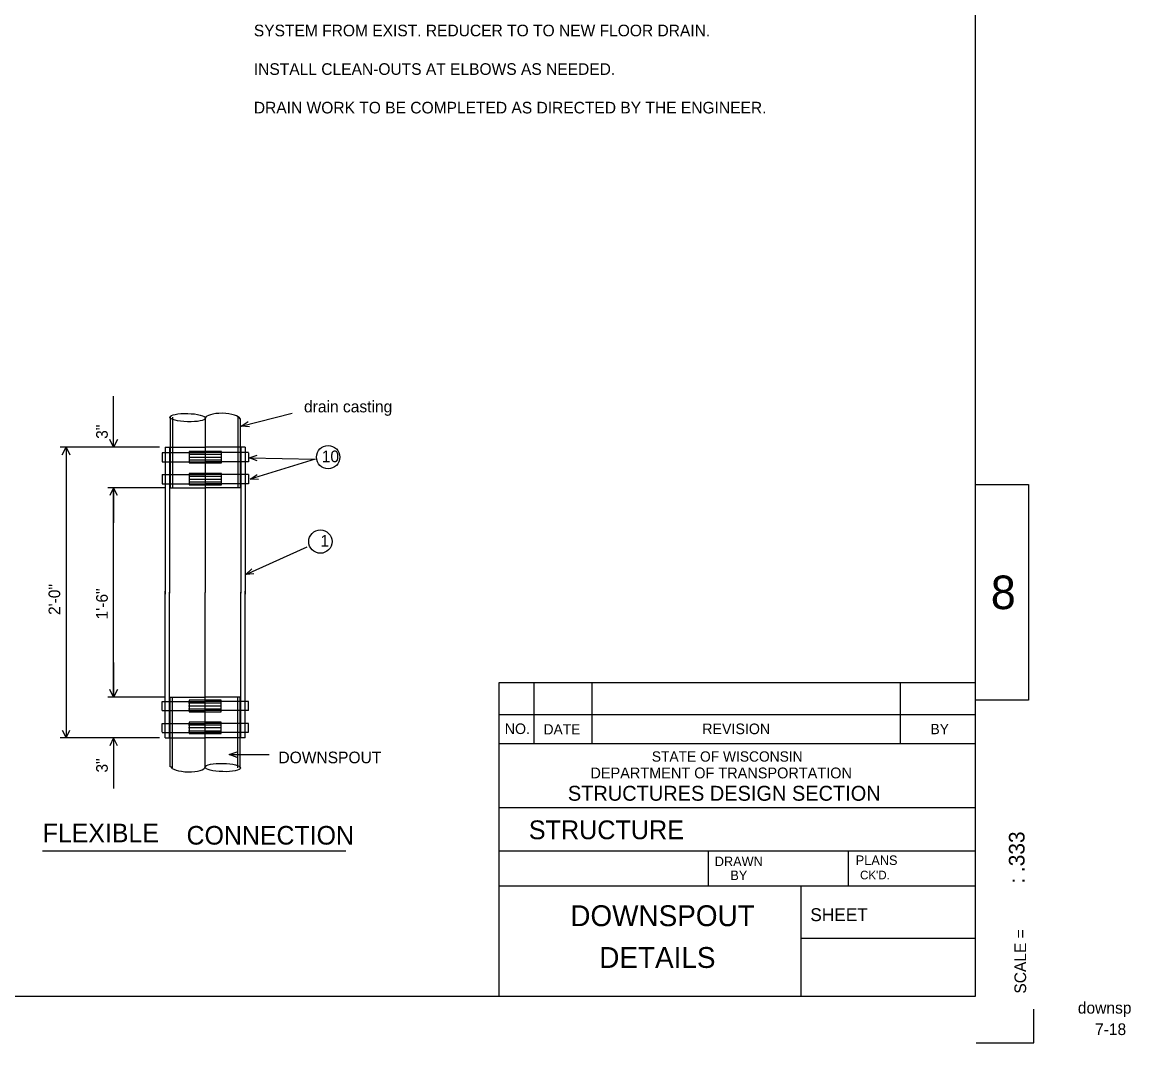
# Model space of a CAD drawing. Extents: x 15000 to 15012.1, y 999.8 to 1007.9.
# Drawn here: x 15008.092 to 15012.061, y 1000.122 to 1003.777 of the extents above; entities that cross this region are included whole.
import ezdxf

# ---------------------------------------------------------------- set-up
doc = ezdxf.new("R2010")
doc.units = 0
doc.layers.add('Level 1', color=7, linetype='Continuous')
doc.layers.add('Level 2', color=7, linetype='Continuous')

msp = doc.modelspace()

# ---------------------------------------------------------------- linework, layer by layer
at = {"layer": 'Level 1'}
for p, q in [((15011.5058, 1000.2885), (15011.5058, 1007.2814)), ((15009.7995, 1001.4123), (15011.507, 1001.4123)), ((15009.7995, 1001.1938), (15009.7995, 1001.4123)), ((15009.9255, 1001.1938), (15009.9255, 1001.4123)), ((15010.1336, 1001.1938), (15010.1336, 1001.4123)), ((15011.2365, 1001.1938), (15011.2365, 1001.4123)), ((15009.7995, 1001.2978), (15011.507, 1001.2978)), ((15009.7995, 1000.2885), (15009.7995, 1001.1938)), ((15009.7995, 1001.1938), (15011.507, 1001.1938)), ((15009.7995, 1000.965), (15011.507, 1000.965)), ((15009.7995, 1000.8089), (15011.507, 1000.8089)), ((15010.5489, 1000.684), (15010.5489, 1000.8089)), ((15011.0506, 1000.684), (15011.0506, 1000.8089)), ((15009.7995, 1000.684), (15011.507, 1000.684)), ((15010.8816, 1000.2885), (15010.8816, 1000.6839)), ((15010.8818, 1000.4966), (15011.5058, 1000.4966)), ((15001.0578, 1000.2885), (15011.5058, 1000.2885)), ((15011.714, 1000.122), (15011.714, 1000.2428)), ((15011.5083, 1000.122), (15011.714, 1000.122))]:
    msp.add_line(p, q, dxfattribs=at)
msp.add_lwpolyline([(15011.5059, 1002.1216), (15011.6948, 1002.1216), (15011.6948, 1001.3486), (15011.5059, 1001.3486)], close=True, dxfattribs=at)
at = {"layer": 'Level 2'}
for p, q in [((15008.4198, 1002.2546), (15008.4198, 1002.4371)), ((15008.6228, 1002.3621), (15008.6228, 1002.2546)), ((15008.6309, 1002.3617), (15008.6309, 1002.1096)), ((15008.7478, 1002.3643), (15008.7478, 1001.7342)), ((15008.8648, 1002.3617), (15008.8648, 1002.1096)), ((15008.8728, 1002.3576), (15008.8728, 1002.2546)), ((15008.8761, 1002.3304), (15009.0593, 1002.3762)), ((15008.8761, 1002.3304), (15008.9011, 1002.3467)), ((15008.9058, 1002.3278), (15008.8761, 1002.3304)), ((15008.5841, 1002.2546), (15008.2285, 1002.2546)), ((15008.2493, 1002.2546), (15008.2493, 1001.2137)), ((15008.5841, 1002.2546), (15008.3989, 1002.2546)), ((15008.5934, 1002.2353), (15008.6921, 1002.2353)), ((15008.5934, 1002.2342), (15008.5934, 1002.2025)), ((15008.6049, 1002.2546), (15008.748, 1002.2546)), ((15008.6049, 1002.2546), (15008.6049, 1002.2342)), ((15008.6049, 1002.2339), (15008.6049, 1002.2037)), ((15008.6049, 1002.2331), (15008.6049, 1002.2038)), ((15008.6204, 1002.2546), (15008.6204, 1001.7326)), ((15008.6228, 1002.2546), (15008.6228, 1002.1092)), ((15008.8072, 1002.2288), (15008.6912, 1002.2288)), ((15008.6921, 1002.2353), (15008.7473, 1002.2353)), ((15008.8908, 1002.2546), (15008.7477, 1002.2546)), ((15008.8058, 1002.2353), (15008.7483, 1002.2353)), ((15008.9023, 1002.2353), (15008.8058, 1002.2353)), ((15008.8728, 1002.2546), (15008.8728, 1002.1092)), ((15008.8752, 1002.2546), (15008.8752, 1001.7326)), ((15008.8908, 1002.2546), (15008.8908, 1002.2342)), ((15008.8908, 1002.2339), (15008.8908, 1002.2037)), ((15008.8908, 1002.2331), (15008.8908, 1002.2038)), ((15008.9023, 1002.2342), (15008.9023, 1002.2025)), ((15008.5934, 1002.2025), (15008.6921, 1002.2025)), ((15008.6049, 1002.2021), (15008.6049, 1002.1568)), ((15008.8072, 1002.2178), (15008.6912, 1002.2178)), ((15008.8072, 1002.2078), (15008.6912, 1002.2078)), ((15008.6921, 1002.2025), (15008.7475, 1002.2025)), ((15008.8058, 1002.2025), (15008.7481, 1002.2025)), ((15008.9023, 1002.2025), (15008.8058, 1002.2025)), ((15008.8908, 1002.2021), (15008.8908, 1002.1568)), ((15008.9054, 1002.2168), (15008.9338, 1002.2258)), ((15008.9054, 1002.2168), (15009.1418, 1002.2113)), ((15008.9333, 1002.2063), (15008.9054, 1002.2168)), ((15009.1418, 1002.2113), (15008.9091, 1002.1398)), ((15008.5934, 1002.1568), (15008.5934, 1002.124)), ((15008.5934, 1002.1568), (15008.6921, 1002.1568)), ((15008.6049, 1002.1554), (15008.6049, 1002.1251)), ((15008.8072, 1002.1502), (15008.6912, 1002.1502)), ((15008.6921, 1002.1568), (15008.7473, 1002.1568)), ((15008.8058, 1002.1568), (15008.7483, 1002.1568)), ((15008.9023, 1002.1568), (15008.8058, 1002.1568)), ((15008.8908, 1002.1554), (15008.8908, 1002.1251)), ((15008.9023, 1002.1568), (15008.9023, 1002.124)), ((15008.9091, 1002.1398), (15008.9332, 1002.1573)), ((15008.602, 1002.1092), (15008.3989, 1002.1092)), ((15008.4198, 1001.3592), (15008.4198, 1002.1092)), ((15008.4198, 1002.1092), (15008.4198, 1001.9842)), ((15008.5934, 1002.124), (15008.6921, 1002.124)), ((15008.6049, 1002.1243), (15008.6049, 1001.7288)), ((15008.6228, 1002.1092), (15008.7462, 1002.1092)), ((15008.8072, 1002.1393), (15008.6912, 1002.1393)), ((15008.8072, 1002.1293), (15008.6912, 1002.1293)), ((15008.6921, 1002.124), (15008.7475, 1002.124)), ((15008.8058, 1002.124), (15008.7481, 1002.124)), ((15008.8728, 1002.1092), (15008.7495, 1002.1092)), ((15008.9023, 1002.124), (15008.8058, 1002.124)), ((15008.8908, 1002.1243), (15008.8908, 1001.7288)), ((15008.9389, 1002.1388), (15008.9091, 1002.1398)), ((15008.8926, 1001.7989), (15009.1125, 1001.8978)), ((15008.8926, 1001.7989), (15008.9143, 1001.8193)), ((15008.9223, 1001.8016), (15008.8926, 1001.7989)), ((15008.6049, 1001.344), (15008.6049, 1001.7395)), ((15008.6204, 1001.2137), (15008.6204, 1001.7357)), ((15008.7478, 1001.104), (15008.7478, 1001.7342)), ((15008.8752, 1001.2137), (15008.8752, 1001.7357)), ((15008.8908, 1001.344), (15008.8908, 1001.7395)), ((15008.4198, 1001.4842), (15008.4198, 1001.3592)), ((15008.602, 1001.3592), (15008.3989, 1001.3592)), ((15008.6228, 1001.3592), (15008.7462, 1001.3592)), ((15008.6228, 1001.2137), (15008.6228, 1001.3592)), ((15008.6309, 1001.1066), (15008.6309, 1001.3587)), ((15008.8728, 1001.3592), (15008.7495, 1001.3592)), ((15008.8648, 1001.1066), (15008.8648, 1001.3587)), ((15008.8728, 1001.2137), (15008.8728, 1001.3592)), ((15008.5934, 1001.3116), (15008.5934, 1001.3443)), ((15008.5934, 1001.3443), (15008.6898, 1001.3443)), ((15008.6049, 1001.3129), (15008.6049, 1001.3432)), ((15008.6884, 1001.3391), (15008.8044, 1001.3391)), ((15008.6884, 1001.329), (15008.8044, 1001.329)), ((15008.6884, 1001.3181), (15008.8044, 1001.3181)), ((15008.6898, 1001.3443), (15008.7475, 1001.3443)), ((15008.8036, 1001.3443), (15008.7481, 1001.3443)), ((15008.9023, 1001.3443), (15008.8036, 1001.3443)), ((15008.8908, 1001.3129), (15008.8908, 1001.3432)), ((15008.9023, 1001.3116), (15008.9023, 1001.3443)), ((15008.5934, 1001.3116), (15008.6898, 1001.3116)), ((15008.6049, 1001.2663), (15008.6049, 1001.3116)), ((15008.6898, 1001.3116), (15008.7473, 1001.3116)), ((15008.8036, 1001.3116), (15008.7483, 1001.3116)), ((15008.9023, 1001.3116), (15008.8036, 1001.3116)), ((15008.8908, 1001.2663), (15008.8908, 1001.3116)), ((15008.5934, 1001.2342), (15008.5934, 1001.2658)), ((15008.5934, 1001.2658), (15008.6898, 1001.2658)), ((15008.6049, 1001.2343), (15008.6049, 1001.2647)), ((15008.6049, 1001.2352), (15008.6049, 1001.2645)), ((15008.6884, 1001.2605), (15008.8044, 1001.2605)), ((15008.6884, 1001.2505), (15008.8044, 1001.2505)), ((15008.6884, 1001.2396), (15008.8044, 1001.2396)), ((15008.6898, 1001.2658), (15008.7475, 1001.2658)), ((15008.8036, 1001.2658), (15008.7481, 1001.2658)), ((15008.9023, 1001.2658), (15008.8036, 1001.2658)), ((15008.8908, 1001.2343), (15008.8908, 1001.2647)), ((15008.8908, 1001.2352), (15008.8908, 1001.2645)), ((15008.9023, 1001.2342), (15008.9023, 1001.2658)), ((15008.3989, 1001.2137), (15008.2285, 1001.2137)), ((15008.5841, 1001.2137), (15008.3989, 1001.2137)), ((15008.4198, 1001.2137), (15008.4198, 1001.0325)), ((15008.5934, 1001.233), (15008.6898, 1001.233)), ((15008.6049, 1001.2137), (15008.6049, 1001.2341)), ((15008.6049, 1001.2137), (15008.748, 1001.2137)), ((15008.6228, 1001.1108), (15008.6228, 1001.2137)), ((15008.6898, 1001.233), (15008.7473, 1001.233)), ((15008.8908, 1001.2137), (15008.7477, 1001.2137)), ((15008.8036, 1001.233), (15008.7483, 1001.233)), ((15008.9023, 1001.233), (15008.8036, 1001.233)), ((15008.8728, 1001.1063), (15008.8728, 1001.2137)), ((15008.8908, 1001.2137), (15008.8908, 1001.2341)), ((15008.8339, 1001.1538), (15008.8621, 1001.1636)), ((15008.8339, 1001.1538), (15008.9769, 1001.1538)), ((15008.8621, 1001.1441), (15008.8339, 1001.1538)), ((15008.1657, 1000.8092), (15009.2514, 1000.8092))]:
    msp.add_line(p, q, dxfattribs=at)
for points in [[(15008.4337, 1002.2823), (15008.4198, 1002.2546), (15008.4058, 1002.2823)], [(15008.2354, 1002.2268), (15008.2493, 1002.2546), (15008.2633, 1002.2268)], [(15008.4337, 1002.0814), (15008.4198, 1002.1092), (15008.4058, 1002.0814)], [(15008.4337, 1002.0814), (15008.4198, 1002.1092), (15008.4058, 1002.0814)], [(15008.4337, 1001.3869), (15008.4198, 1001.3592), (15008.4058, 1001.3869)], [(15008.4337, 1001.3869), (15008.4198, 1001.3592), (15008.4058, 1001.3869)], [(15008.2354, 1001.2414), (15008.2493, 1001.2137), (15008.2633, 1001.2414)], [(15008.4337, 1001.1859), (15008.4198, 1001.2137), (15008.4058, 1001.1859)]]:
    msp.add_lwpolyline(points, dxfattribs=at)
for points in [[(15008.8058, 1002.1982), (15008.8058, 1002.1999), (15008.8058, 1002.2366), (15008.8058, 1002.2392), (15008.6908, 1002.2392), (15008.6908, 1002.1982)], [(15008.8058, 1002.1197), (15008.8058, 1002.1214), (15008.8058, 1002.158), (15008.8058, 1002.1607), (15008.6908, 1002.1607), (15008.6908, 1002.1197)], [(15008.6898, 1001.3487), (15008.6898, 1001.3469), (15008.6898, 1001.3103), (15008.6898, 1001.3077), (15008.8049, 1001.3077), (15008.8049, 1001.3487)], [(15008.6898, 1001.2701), (15008.6898, 1001.2683), (15008.6898, 1001.2318), (15008.6898, 1001.2291), (15008.8049, 1001.2291), (15008.8049, 1001.2701)]]:
    msp.add_lwpolyline(points, close=True, dxfattribs=at)
for centre in [(15009.1877, 1002.219), (15009.1599, 1001.9167)]:
    msp.add_circle(centre, 0.0417, dxfattribs=at)
for centre, major_axis in [((15008.6848, 1002.3605), (0.0634, -0.0016)), ((15008.8108, 1001.1078), (-0.0634, 0.0016))]:
    msp.add_ellipse(centre, major_axis=major_axis, ratio=0.234609, dxfattribs=at)
for centre, major_axis in [((15008.8104, 1002.3564), (0.062, -0.0016)), ((15008.6852, 1001.1119), (-0.062, 0.0016))]:
    msp.add_ellipse(centre, major_axis=major_axis, ratio=0.314672, start_param=0.070448, end_param=3.13618, dxfattribs=at)

# ---------------------------------------------------------------- texts
at = {"layer": 'Level 1'}
for s, height, p in [('8', 0.1202, (15011.5601, 1001.6749)), ('NO.', 0.03794, (15009.8201, 1001.2276)), ('DATE', 0.03691, (15009.9591, 1001.226)), ('REVISION', 0.03802, (15010.5273, 1001.2272)), ('BY', 0.03691, (15011.3443, 1001.2271)), ('STATE OF WISCONSIN', 0.036882, (15010.3466, 1001.1288)), ('DEPARTMENT OF TRANSPORTATION', 0.03877, (15010.1268, 1001.0689)), ('STRUCTURES DESIGN SECTION', 0.053447, (15010.0461, 1000.9888)), ('STRUCTURE', 0.06735, (15009.9062, 1000.851)), ('DRAWN', 0.03405, (15010.572, 1000.7546)), ('PLANS', 0.03408, (15011.0766, 1000.7588)), ('BY', 0.03397, (15010.6278, 1000.7048)), ("CK'D.", 0.03086, (15011.0921, 1000.7073)), ('DOWNSPOUT', 0.07467, (15010.0548, 1000.5398)), ('SHEET', 0.04618, (15010.9139, 1000.5577)), ('DETAILS', 0.07467, (15010.1584, 1000.3902))]:
    msp.add_text(s, height=height, dxfattribs=at).set_placement(p)
for s, height, p in [(': .333', 0.05592, (15011.6809, 1000.6918)), ('SCALE =          ', 0.041625, (15011.6866, 1000.2982))]:
    msp.add_text(s, height=height, rotation=90, dxfattribs=at).set_placement(p)
at = {"layer": 'Level 2'}
for s, height, p in [('SYSTEM FROM EXIST. REDUCER TO TO NEW FLOOR DRAIN.', 0.041651, (15008.9218, 1003.7259)), ('INSTALL CLEAN-OUTS AT ELBOWS AS NEEDED.', 0.041651, (15008.9218, 1003.5878)), ('DRAIN WORK TO BE COMPLETED AS DIRECTED BY THE ENGINEER.', 0.041651, (15008.9218, 1003.4497)), ('drain casting', 0.041667, (15009.1014, 1002.3794)), ('10', 0.04167, (15009.1649, 1002.2009)), ('1', 0.0417, (15009.1601, 1001.8986)), ('DOWNSPOUT', 0.04167, (15009.0098, 1001.123)), ('FLEXIBLE', 0.06667, (15008.1657, 1000.84)), ('CONNECTION', 0.06667, (15008.6809, 1000.8318)), ('downsp', 0.04167, (15011.8717, 1000.2266)), ('7-18', 0.04167, (15011.9333, 1000.1498))]:
    msp.add_text(s, height=height, dxfattribs=at).set_placement(p)
for s, p in [(' 3" ', (15008.3989, 1002.2691)), (' 2\'-0" ', (15008.2285, 1001.6383)), ('1\'-6"', (15008.3989, 1001.6381)), (' 3" ', (15008.3989, 1001.0742))]:
    msp.add_text(s, height=0.04167, rotation=90, dxfattribs=at).set_placement(p)

doc.saveas('drawing.dxf')
